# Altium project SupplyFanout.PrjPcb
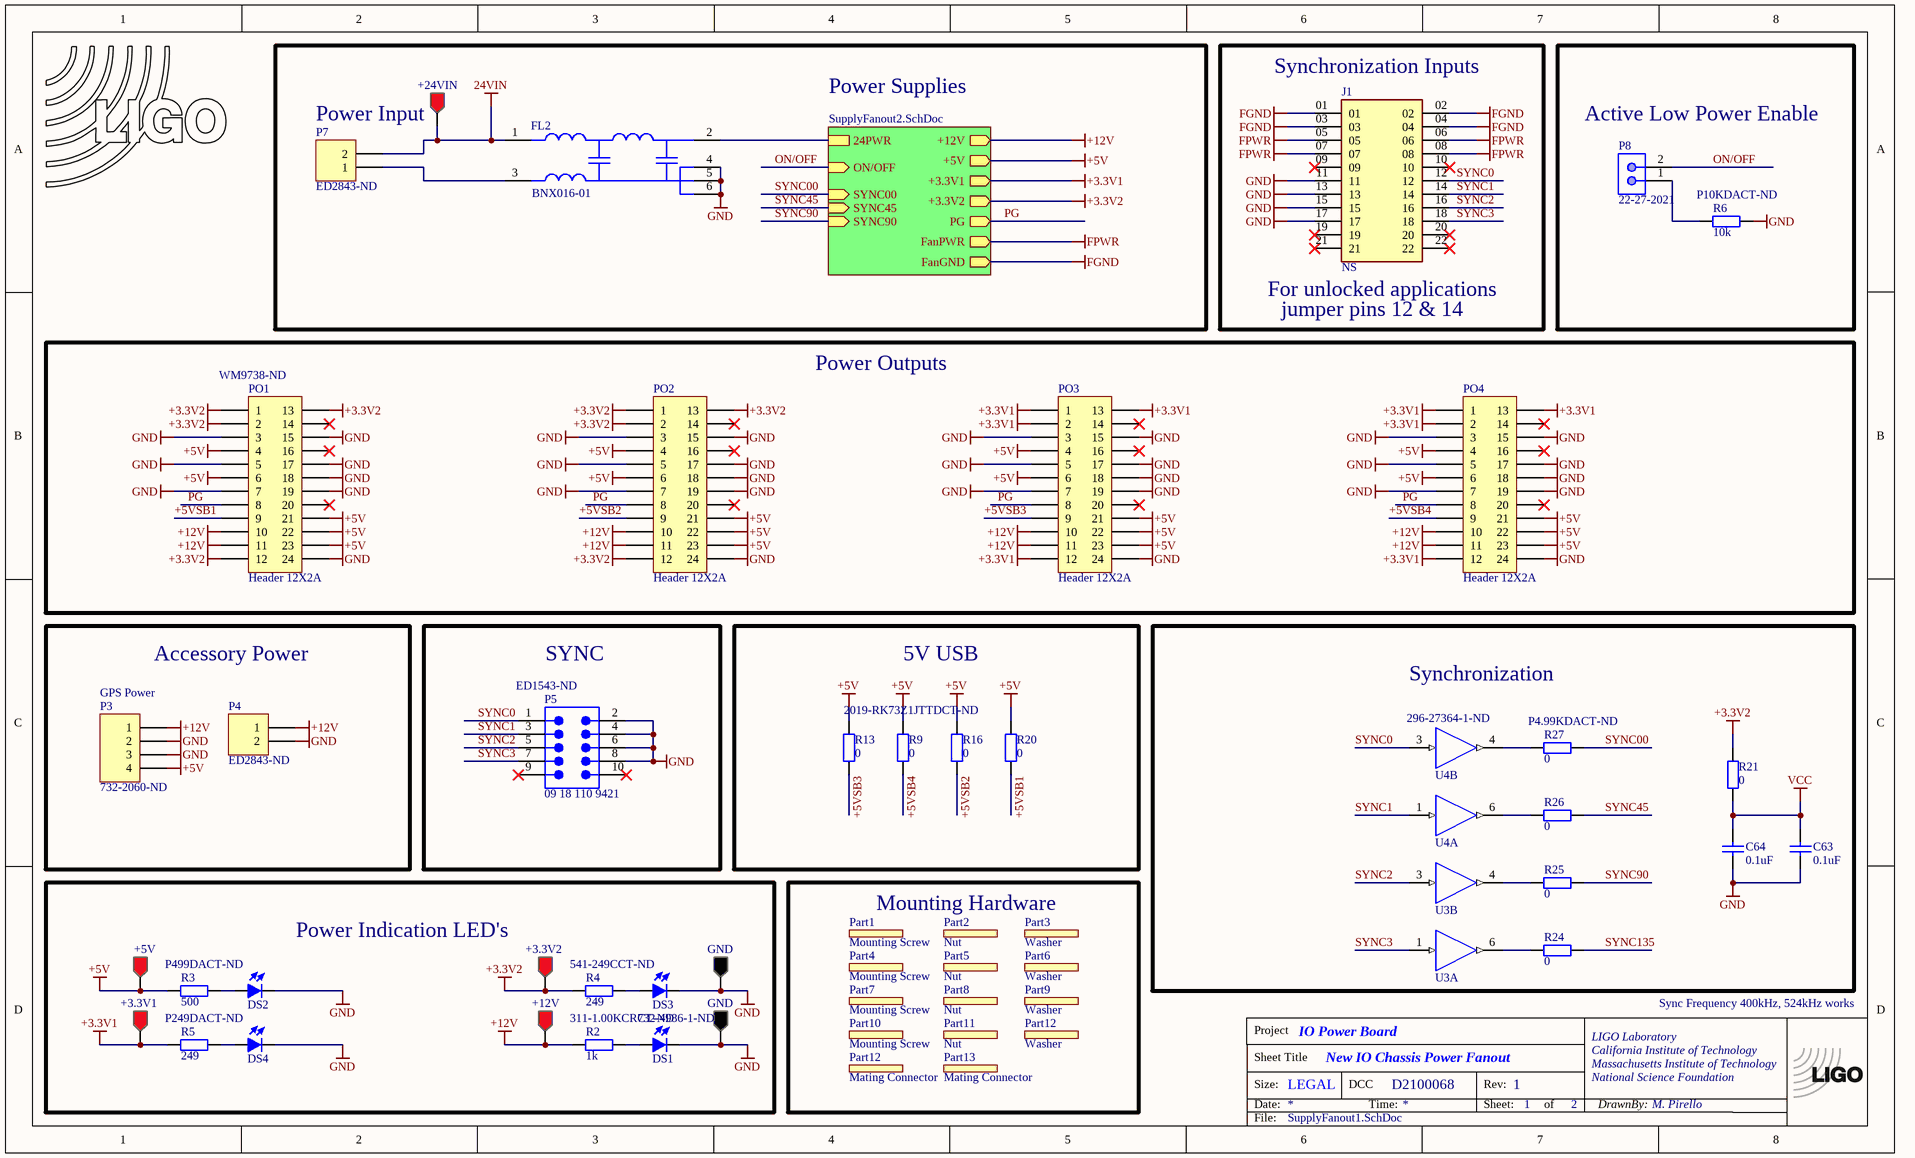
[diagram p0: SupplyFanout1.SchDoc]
DCC: D2100068; Eng: M. Pirello; PROJECT: IO Power Board; REV: 1; SHEETSIZE: LEGAL
2 sheets, 168 parts. Net scope: hierarchical (ports join the sheet entries above them; power ports are global).
Board file: SupplyFanout_30inch.PcbDoc
Sheets:
  SupplyFanout1.SchDoc
    Power Supplies = SupplyFanout2.SchDoc

## Sheet SupplyFanout1.SchDoc: New IO Chassis Power Fanout
size Legal; Organization: LIGO Project; Address1: California Institute of Technology; Address2: Massachusetts Institute of technology; DocumentNumber: D1800033; Revision: v1; SheetNumber: 1; SheetTotal: 2; Author: .Ben Abbott; DrawnBy: .Ben Abbott; Engineer: M. Pirello

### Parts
(Parts that share a designator on the sheet are numbered #1, #2 ... from top to bottom, then left to right.)
*?#1  TitleBlock  (value not drawn)  (graphical)
+3.3V1  Testpoint  [TP1-RED]  (value not drawn)
+3.3V2  Testpoint  [TP1-RED]  (value not drawn)
+5V  Testpoint  [TP1-RED]  (value not drawn)
+12V  Testpoint  [TP1-RED]  (value not drawn)
+24VIN  Testpoint  [TP1-RED]  (value not drawn)
C63  0.1uF  [CC1608-0603]
C64  0.1uF  [CC1608-0603]
DS1  Supplier Part Number 1: 732-4986-1-ND  [LED-0805]  (hidden comment: LED)
DS2  LED  [LED-0805]  (value not drawn)
DS3  LED  [LED-0805]  (value not drawn)
DS4  LED  [LED-0805]  (value not drawn)
FL2  BNX016-01  [MURA-BNX016-01_V]
GND#1  Testpoint  [TP1-BLK]  (value not drawn)
GND#2  Testpoint  [TP1-BLK]  (value not drawn)
J1  NS  [SAMTEC_SSW-111-02-G-D-RA]
LOGO2  LIGO logo  [LIGO-LOGO-SM]  (value not drawn)  (no BOM)
P3  Supplier Part Number 1: 732-2060-ND  [SL_5_08HC_180B_04]  (hidden comment: TBlock_5.08_4)
P4  Supplier Part Number 1: ED2843-ND  [SL_5_08HC_180B_02]  (hidden comment: TBlock_5.08_2)
P5  09 18 110 9421  Supplier Part Number 1: ED1543-ND  [9181109421]
P7  Supplier Part Number 1: ED2843-ND  [SL_5_08HC_180B_02]  (hidden comment: TBlock_5.08_2)
P8  22-27-2021  [MOLX-22-27-2021_V]
Part1  Mounting Screw  (mechanical)
Part2  Nut  (mechanical)
Part3  Washer  (mechanical)
Part4  Mounting Screw  (mechanical)
Part5  Nut  (mechanical)
Part6  Washer  (mechanical)
Part7  Mounting Screw  (mechanical)
Part8  Nut  (mechanical)
Part9  Washer  (mechanical)
Part10  Mounting Screw  (mechanical)
Part11  Nut  (mechanical)
Part12#1  Washer  (mechanical)
Part12#2  Mating Connector  (mechanical)
Part13  Mating Connector  (mechanical)
PO1  Header 12X2A  Supplier Part Number 1: WM9738-ND  [ATX24Pin_M]
PO2  Header 12X2A  [ATX24Pin_M]
PO3  Header 12X2A  [ATX24Pin_M]
PO4  Header 12X2A  [ATX24Pin_M]
R2  Supplier Part Number 1: 311-1.00KCRCT-ND  [CR2012-0805]  (hidden comment: 1k)
R3  Supplier Part Number 1: P499DACT-ND  [CR2012-0805]  (hidden comment: 500)
R4  Supplier Part Number 1: 541-249CCT-ND  [CR2012-0805]  (hidden comment: 249)
R5  Supplier Part Number 1: P249DACT-ND  [CR2012-0805]  (hidden comment: 249)
R6  Supplier Part Number 1: P10KDACT-ND  [CR2012-0805]  (hidden comment: 10k)
R9  0  [CR1608-0603]
R13  Supplier Part Number 1: 2019-RK73Z1JTTDCT-ND  [CR1608-0603]  (hidden comment: 0)
R16  0  [CR1608-0603]
R20  0  [CR1608-0603]
R21  0  [CR3216-1206]
R24  0  [CR3216-1206]
R25  0  [CR3216-1206]
R26  0  [CR3216-1206]
R27  Supplier Part Number 1: P4.99KDACT-ND  [CR3216-1206]  (hidden comment: 0)
U3  SN74LVC2G34  [SO-G6/E2.4]  (value not drawn)  (parts A,B of 2)
U4  SN74LVC2G34  [SO-G6/E2.4]  (value not drawn)  (parts A,B of 2)

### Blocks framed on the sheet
Power Input: +24VIN FL2 P7
Active Low Power Enable: P8 R6
Power Outputs: PO1-PO4
Accessory Power: P3 P4
SYNC: P5
5V USB: R9 R13 R16 R20
Synchronization: C63 C64 R21 R24-R27 U3 U4
Power Indication LED's: +3.3V1 +3.3V2 +5V +12V DS1-DS4 GND#1 GND#2 R2-R5
Mounting Hardware: Part1-Part11 Part12#1 Part12#2 Part13

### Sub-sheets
Power Supplies = SupplyFanout2.SchDoc: 24PWR, SYNC00 (in), SYNC45 (in), SYNC90 (in), ON/OFF (in), PG (out), +3.3V1 (out), +3.3V2 (out), +5V (out), +12V (out), FanPWR (out), FanGND (out)

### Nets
24VIN: +24VIN.1 FL2.1(B) P7.2
+3.3V1: +3.3V1.1 PO3.1 PO3.2 PO3.12 PO3.13 PO4.1 PO4.2 PO4.12 PO4.13 R5.1 ; sheet Power Supplies/+3.3V1
+3.3V2: +3.3V2.1 PO1.1 PO1.2 PO1.12 PO1.13 PO2.1 PO2.2 PO2.12 PO2.13 R4.1 R21.1 ; sheet Power Supplies/+3.3V2
+5V: +5V.1 P3.4 PO1.4 PO1.6 PO1.21 PO1.22 PO1.23 PO2.4 PO2.6 PO2.21 PO2.22 PO2.23 PO3.4 PO3.6 PO3.21 PO3.22 PO3.23 PO4.4 PO4.6 PO4.21 PO4.22 PO4.23 R3.1 R9.1 R13.1 R16.1 R20.1 ; sheet Power Supplies/+5V
+12V: +12V.1 P3.1 P4.1 PO1.10 PO1.11 PO2.10 PO2.11 PO3.10 PO3.11 PO4.10 PO4.11 R2.1 ; sheet Power Supplies/+12V
FGND: J1.01 J1.02 J1.03 J1.04 ; sheet Power Supplies/FanGND
FPWR: J1.05 J1.06 J1.07 J1.08 ; sheet Power Supplies/FanPWR
GND: C63.1 C64.1 DS1.1(K) DS2.1(K) DS3.1(K) DS4.1(K) FL2.4(CG) FL2.5(CG) FL2.6(CG) GND#1.1 GND#2.1 J1.11 J1.13 J1.15 J1.17 P3.2 P3.3 P4.2 P5.2 P5.4 P5.6 P5.8 PO1.3 PO1.5 PO1.7 PO1.15 PO1.17 PO1.18 PO1.19 PO1.24 PO2.3 PO2.5 PO2.7 PO2.15 PO2.17 PO2.18 PO2.19 PO2.24 PO3.3 PO3.5 PO3.7 PO3.15 PO3.17 PO3.18 PO3.19 PO3.24 PO4.3 PO4.5 PO4.7 PO4.15 PO4.17 PO4.18 PO4.19 PO4.24 R6.1 U3.2(GND) U4.2(GND)
VCC: C63.2 C64.2 R21.2 U3.5(VCC) U4.5(VCC)
+5VSB1: PO1.9 R20.2
+5VSB2: PO2.9 R16.2
+5VSB3: PO3.9 R13.2
+5VSB4: PO4.9 R9.2
ON/OFF: P8.2 ; sheet Power Supplies/ON/OFF
PG: PO1.8 PO2.8 PO3.8 PO4.8 ; sheet Power Supplies/PG
SYNC00: R27.1 ; sheet Power Supplies/SYNC00
SYNC0: J1.12 P5.1 U4.3(2A)
SYNC1: J1.14 P5.3 U4.1(1A)
SYNC2: J1.16 P5.5 U3.3(2A)
SYNC3: J1.18 P5.7 U3.1(1A)
SYNC45: R26.1 ; sheet Power Supplies/SYNC45
SYNC90: R25.1 ; sheet Power Supplies/SYNC90
SYNC135: R24.1
Net+24V_1: FL2.2(CB) ; sheet Power Supplies/24PWR
NetDS1_2: DS1.2(A) R2.2
NetDS2_2: DS2.2(A) R3.2
NetDS3_2: DS3.2(A) R4.2
NetDS4_2: DS4.2(A) R5.2
NetFL2_3: FL2.3(PSG) P7.1
NetP8_1: P8.1 R6.2
NetR24_2: R24.2 U3.6(1Y)
NetR25_2: R25.2 U3.4(2Y)
NetR26_2: R26.2 U4.6(1Y)
NetR27_2: R27.2 U4.4(2Y)

Not connected (* = marked no-connect by the designer): J1 09* 10* 19* 20* 21* 22*; P5 9* 10*; PO1 14* 16* 20*; PO2 14* 16* 20*; PO3 14* 16* 20*; PO4 14* 16* 20*

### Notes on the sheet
- (near J1) Synchronization Inputs
- (near J1) For unlocked applications
- (near J1) jumper pins 12 & 14
- (near P3) GPS Power
- Sync Frequency 400kHz, 524kHz works

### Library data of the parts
+3.3V1 +3.3V2 +5V +12V +24VIN = TP_POSITIVE: Testpoint, red; Part Number: 36-5005-ND
C63 C64 = ChipCap: Capacitor, surface mount; Tolerance: 10%
DS1-DS4 = LED: Panel mount LED
FL2 = CMP-2000-05960-1: Block Type EMIFIL(R) Reference Specification, 15 A, 25 V, -40 to 125 degC, 6-Pin THD, RoHS, Bulk; Part Number: 490-5055-ND
GND#1 GND#2 = TP_GND: Testpoint, black; Part Number: 36-5006-ND
J1 = SSW-111-02-G-D-RA: MF: Samtec Inc.
LOGO2 = LIGO_logo
P3 = TBlock_5.08_4: Terminal block, 5.08mm, 4-Pin; Part Number: 281-1299-ND
P4 P7 = TBlock_5.08_2: Terminal block, 5.08mm, 2-Pin; Part Number: 281-1297-ND
P5 = 09 18 110 9421: Flat Cable Connector (IDC), PCB Transition Connector, 2 Rows, Kinked Solder Pin, 10 Contacts; PCB_Layout: Complies with manufacturer's recommendation.; DrillSize: Corresponds to nominal value.
P8 = CMP-2000-05537-1: Male Header, Pitch 2.54 mm, 1 x 2 Position, Height 11.7 mm, Tail Length 3.56 mm, 0 to 75 degC, RoHS, Bulk; Manufacturer: Molex; PartNumber: 0022272021; Current rating: 4A; Package Version: Rev. BC, 02/2012; Voltage rating: 250V; No. of Positions: 2; Pitch: 2.54mm; No. of Rows: 1
Part1 Part4 Part7 Part10 = Mechanical Part: Mounting Screw for Inductors
Part2 Part5 Part8 Part11 = Mechanical Part: Nut for Inductor Mounting Screw
Part3 Part6 Part9 Part12#1 Part12#2 Part13 = Mechanical Part: To go under nut for Inductor Mounting Screw
PO1 = ATX24PIN_MALE: Header, 12-Pin, Dual row, ATX power, board
PO2-PO4 = ATX24PIN_MALE: Header, 12-Pin, Dual row, ATX power, board; Part Number: WM9738-ND
R2-R6 R9 R13 R16 R20 R21 R24-R27 = ChipRes1: Resistor, surface mount; Tolerance: 1%
U3 U4 = SN74LVC2G34: Dual buffer

## Sheet SupplyFanout2.SchDoc: New IO Chassis Power Fanout
size Legal; Organization: LIGO Project; Address1: California Institute of Technology; Address2: Massachusetts Institute of technology; DocumentNumber: D1800033; Revision: v1; SheetNumber: 2; SheetTotal: 2; Author: .Ben Abbott; DrawnBy: .Ben Abbott; Engineer: M. Pirello
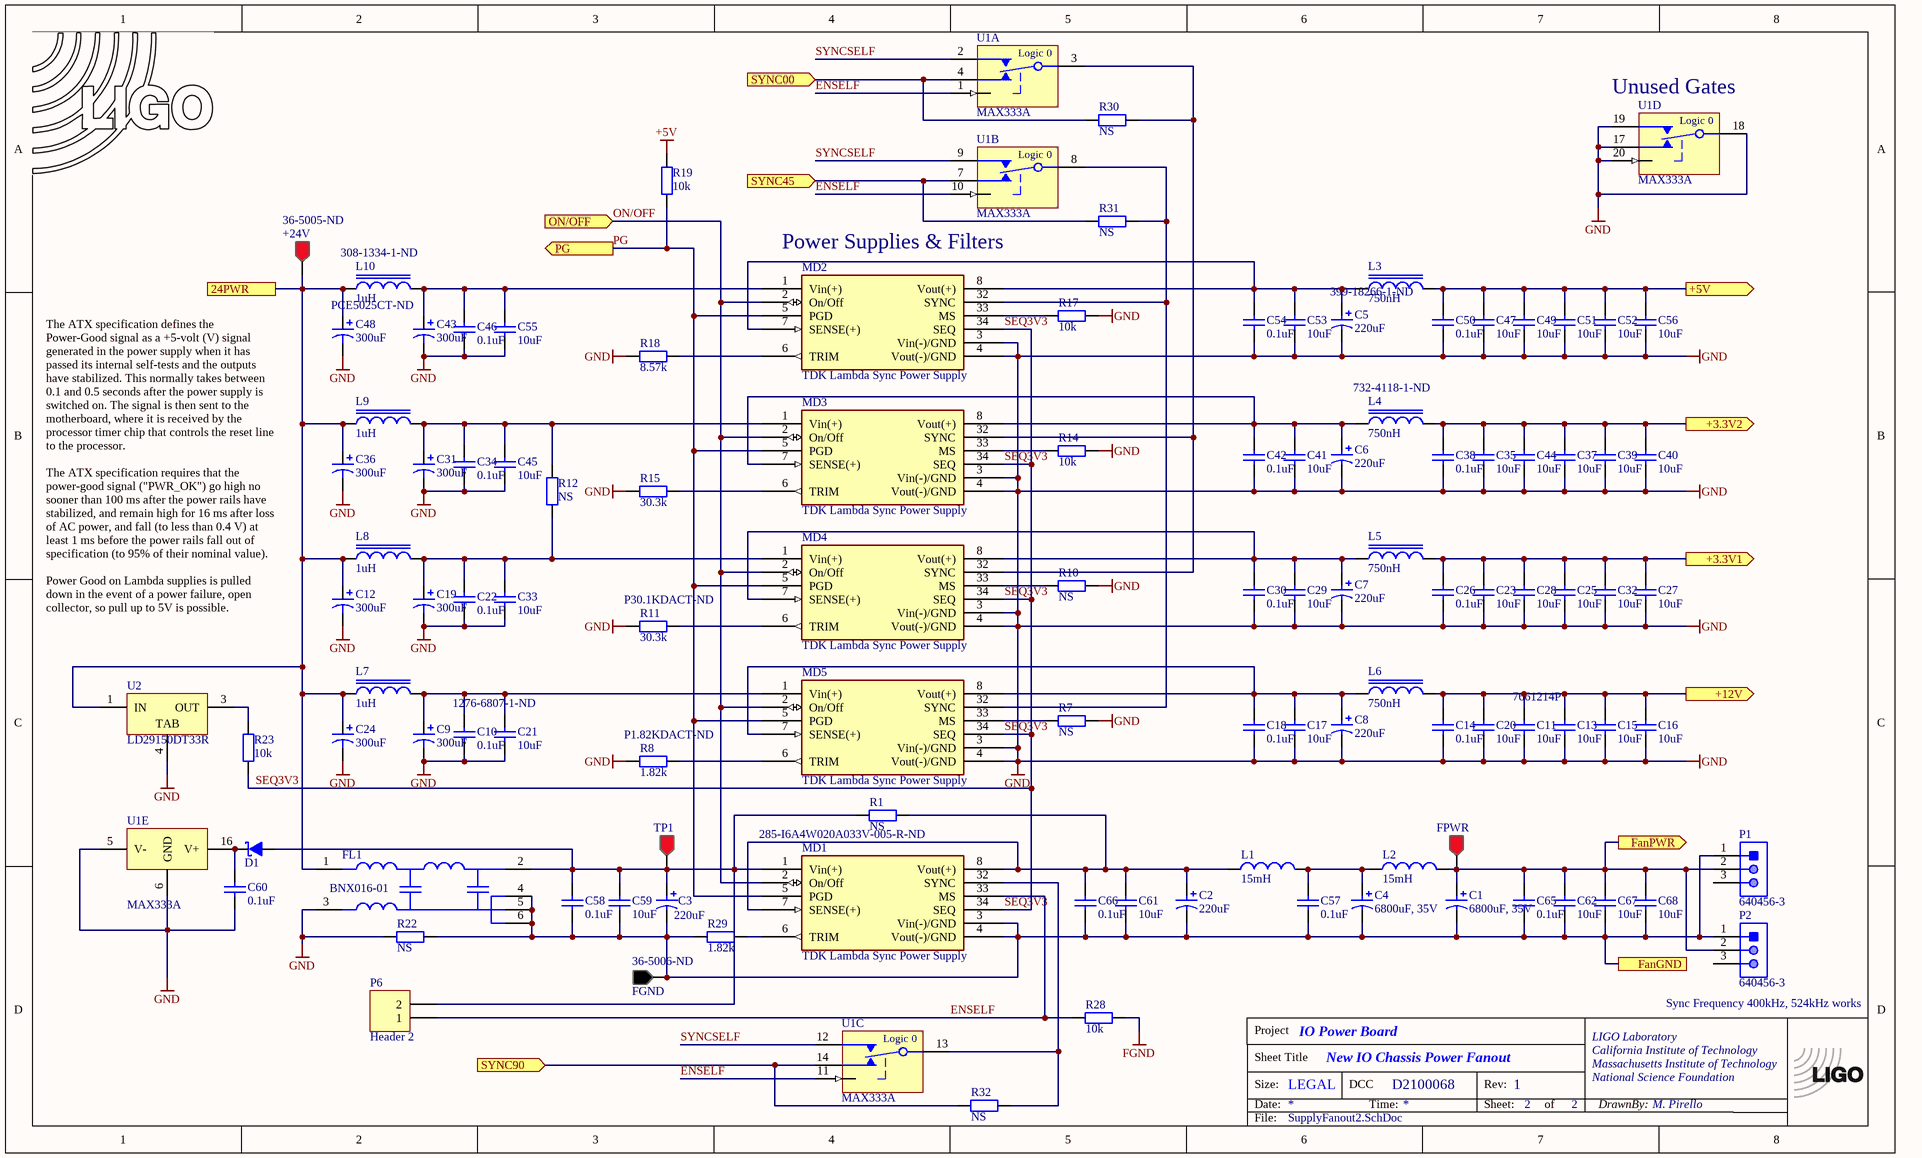
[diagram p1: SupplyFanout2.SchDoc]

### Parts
(Parts that share a designator on the sheet are numbered #1, #2 ... from top to bottom, then left to right.)
*?#2  TitleBlock  (value not drawn)  (graphical)
+24V  Supplier Part Number 1: 36-5005-ND  [TP1-RED]  (hidden comment: Testpoint)
C1  6800uF, 35V  [RB18/7.5]
C2  220uF  [RB10/5.0]
C3  220uF  [RB10/5.0]
C4  6800uF, 35V  [RB18/7.5]
C5  Supplier Part Number 1: 399-18266-1-ND  [RB10/5.0]  (hidden comment: 220uF)
C6  220uF  [RB10/5.0]
C7  220uF  [RB10/5.0]
C8  220uF  [RB10/5.0]
C9  300uF  [AC083-033/E]
C10  Supplier Part Number 1: 1276-6807-1-ND  [CC1608-0603]  (hidden comment: 0.1uF)
C11  Supplier Part Number 1: 7661214P  [CC3225-1210]  (hidden comment: 10uF)
C12  300uF  [AC083-033/E]
C13  10uF  [CC3225-1210]
C14  0.1uF  [CC1608-0603]
C15  10uF  [CC3225-1210]
C16  10uF  [CC3225-1210]
C17  10uF  [CC3225-1210]
C18  0.1uF  [CC1608-0603]
C19  300uF  [AC083-033/E]
C20  10uF  [CC3225-1210]
C21  10uF  [CC3225-1210]
C22  0.1uF  [CC1608-0603]
C23  10uF  [CC3225-1210]
C24  300uF  [AC083-033/E]
C25  10uF  [CC3225-1210]
C26  0.1uF  [CC1608-0603]
C27  10uF  [CC3225-1210]
C28  10uF  [CC3225-1210]
C29  10uF  [CC3225-1210]
C30  0.1uF  [CC1608-0603]
C31  300uF  [AC083-033/E]
C32  10uF  [CC3225-1210]
C33  10uF  [CC3225-1210]
C34  0.1uF  [CC1608-0603]
C35  10uF  [CC3225-1210]
C36  300uF  [AC083-033/E]
C37  10uF  [CC3225-1210]
C38  0.1uF  [CC1608-0603]
C39  10uF  [CC3225-1210]
C40  10uF  [CC3225-1210]
C41  10uF  [CC3225-1210]
C42  0.1uF  [CC1608-0603]
C43  300uF  [AC083-033/E]
C44  10uF  [CC3225-1210]
C45  10uF  [CC3225-1210]
C46  0.1uF  [CC1608-0603]
C47  10uF  [CC3225-1210]
C48  Supplier Part Number 1: PCE5025CT-ND  [AC083-033/E]  (hidden comment: 300uF)
C49  10uF  [CC3225-1210]
C50  0.1uF  [CC1608-0603]
C51  10uF  [CC3225-1210]
C52  10uF  [CC3225-1210]
C53  10uF  [CC3225-1210]
C54  0.1uF  [CC1608-0603]
C55  10uF  [CC3225-1210]
C56  10uF  [CC3225-1210]
C57  0.1uF  [CC1608-0603]
C58  0.1uF  [CC1608-0603]
C59  10uF  [CC3225-1210]
C60  0.1uF  [CC1608-0603]
C61  10uF  [CC3225-1210]
C62  10uF  [CC3225-1210]
C65  0.1uF  [CC1608-0603]
C66  0.1uF  [CC1608-0603]
C67  10uF  [CC3225-1210]
C68  10uF  [CC3225-1210]
D1  shottky diode  [DO-SMA]  (value not drawn)
FGND  Supplier Part Number 1: 36-5006-ND  [TP1-BLK]  (hidden comment: Testpoint)
FL1  BNX016-01  [MURA-BNX016-01_V]
FPWR  Testpoint  [TP1-RED]  (value not drawn)
L1  value 15mH  [Rnd Inductor 45D]  (hidden comment: Inductor)
L2  value 15mH  [Rnd Inductor 45D]  (hidden comment: Inductor)
L3  750nH  [MSS1278]
L4  Supplier Part Number 1: 732-4118-1-ND  [MSS1278]  (hidden comment: 750nH)
L5  750nH  [MSS1278]
L6  750nH  [MSS1278]
L7  1uH  [MSS1278]
L8  1uH  [MSS1278]
L9  1uH  [MSS1278]
L10  Supplier Part Number 1: 308-1334-1-ND  [MSS1278]  (hidden comment: 1uH)
LOGO1  LIGO logo  [LIGO_LOGO]  (value not drawn)  (no BOM)
MD1  TDK Lambda Sync Power Supply  Supplier Part Number 1: 285-I6A4W020A033V-005-R-ND  [TDK-Lambda]
MD2  TDK Lambda Sync Power Supply  [TDK-Lambda]
MD3  TDK Lambda Sync Power Supply  [TDK-Lambda]
MD4  TDK Lambda Sync Power Supply  [TDK-Lambda]
MD5  TDK Lambda Sync Power Supply  [TDK-Lambda]
P1  640456-3  [TECO-640456-3]
P2  640456-3  [TECO-640456-3]
P6  Header 2  [HDR1X2]
R1  NS  [CR3225-1210]
R7  NS  [CR1608-0603]
R8  Supplier Part Number 1: P1.82KDACT-ND  [CR2012-0805]  (hidden comment: 1.82k)
R10  NS  [CR1608-0603]
R11  Supplier Part Number 1: P30.1KDACT-ND  [CR2012-0805]  (hidden comment: 30.3k)
R12  NS  [CR3225-1210]
R14  10k  [CR1608-0603]
R15  30.3k  [CR2012-0805]
R17  10k  [CR1608-0603]
R18  8.57k  [CR2012-0805]
R19  10k  [CR1608-0603]
R22  NS  [CR3225-1210]
R23  10k  [CR1608-0603]
R28  10k  [CR1608-0603]
R29  1.82k  [CR2012-0805]
R30  NS  [CR0603-0201]
R31  NS  [CR0603-0201]
R32  NS  [CR0603-0201]
TP1  Testpoint  [TP1-RED]  (value not drawn)
U1  MAX333A  [SO-G20]  (parts A,B,C,D,E of 5)
U2  LD29150DT33R  [TO-252_L]

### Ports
24PWR, +3.3V1 (out), +3.3V2 (out), +5V (out), +12V (out), FanGND, FanPWR (out), ON/OFF (in), PG (out), SYNC00 (in), SYNC45 (in), SYNC90 (in)

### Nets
+3.3V1: C23.2 C25.2 C26.2 C27.2 C28.2 C32.2 L5.2 ; port +3.3V1
+3.3V2: C35.2 C37.2 C38.2 C39.2 C40.2 C44.2 L4.2 ; port +3.3V2
+5V: C47.2 C49.2 C50.2 C51.2 C52.2 C56.2 L3.2 R19.1 ; port +5V
+12V: C11.2 C13.2 C14.2 C15.2 C16.2 C20.2 L6.2 ; port +12V
FGND: C1.2 C2.2 C3.2 C4.2 C57.1 C58.1 C59.1 C61.1 C62.1 C65.1 C66.1 C67.1 C68.1 FGND.1 FL1.4(CG) FL1.5(CG) FL1.6(CG) MD1.3(Vin(-)/GND) MD1.4(Vout(-)/GND) P1.1 P2.1 R22.1 R28.2 R29.2 ; port FanGND
FPWR: C1.1 C62.2 C65.2 C67.2 C68.2 FPWR.1 L2.1 P1.2 P2.2 ; port FanPWR
GND: C5.2 C6.2 C7.2 C8.2 C9.2 C10.1 C11.1 C12.2 C13.1 C14.1 C15.1 C16.1 C17.1 C18.1 C19.2 C20.1 C21.1 C22.1 C23.1 C24.2 C25.1 C26.1 C27.1 C28.1 C29.1 C30.1 C31.2 C32.1 C33.1 C34.1 C35.1 C36.2 C37.1 C38.1 C39.1 C40.1 C41.1 C42.1 C43.2 C44.1 C45.1 C46.1 C47.1 C48.2 C49.1 C50.1 C51.1 C52.1 C53.1 C54.1 C55.1 C56.1 C60.1 FL1.3(PSG) MD2.3(Vin(-)/GND) MD2.4(Vout(-)/GND) MD3.3(Vin(-)/GND) MD3.4(Vout(-)/GND) MD4.3(Vin(-)/GND) MD4.4(Vout(-)/GND) MD5.3(Vin(-)/GND) MD5.4(Vout(-)/GND) R7.2 R8.2 R10.2 R11.2 R14.2 R15.2 R17.2 R18.2 R22.2 U1.5(V-) U1.6(GND) U1.17(NO4) U1.18(COM4) U1.19(NC4) U1.20(IN4) U2.4(TAB)
ENSELF: MD1.33(MS) P6.1 R28.1 U1.1(IN1) U1.10(IN2) U1.11(IN3)
ON/OFF: MD1.2(On/Off) MD2.2(On/Off) MD3.2(On/Off) MD4.2(On/Off) MD5.2(On/Off) ; port ON/OFF
PG: MD1.5(PGD) MD2.5(PGD) MD3.5(PGD) MD4.5(PGD) MD5.5(PGD) R19.2 ; port PG
SEQ3V3: MD1.34(SEQ) MD2.34(SEQ) MD3.34(SEQ) MD4.34(SEQ) MD5.34(SEQ) R23.1
SYNC00: R30.1 U1.4(NO1) ; port SYNC00
SYNC45: R31.1 U1.7(NO2) ; port SYNC45
SYNC90: R32.1 U1.14(NO3) ; port SYNC90
SYNCSELF: U1.2(NC1) U1.9(NC2) U1.12(NC3)
Net+24V_1: +24V.1 C12.1 C24.1 C36.1 C48.1 FL1.1(B) L7.1 L8.1 L9.1 L10.1 U2.1(IN) ; port 24PWR
NetC2_1: C2.1 C61.2 C66.2 L1.2 MD1.7(SENSE(+)) MD1.8(Vout(+)) R1.1
NetC3_1: C3.1 C58.2 C59.2 D1.1(A) FL1.2(CB) MD1.1(Vin(+)) P6.2 R1.2 TP1.1
NetC4_1: C4.1 C57.2 L1.1 L2.2
NetC5_1: C5.1 C53.2 C54.2 L3.1 MD2.7(SENSE(+)) MD2.8(Vout(+))
NetC6_1: C6.1 C41.2 C42.2 L4.1 MD3.7(SENSE(+)) MD3.8(Vout(+))
NetC7_1: C7.1 C29.2 C30.2 L5.1 MD4.7(SENSE(+)) MD4.8(Vout(+))
NetC8_1: C8.1 C17.2 C18.2 L6.1 MD5.7(SENSE(+)) MD5.8(Vout(+))
NetC9_1: C9.1 C10.2 C21.2 L7.2 MD5.1(Vin(+))
NetC19_1: C19.1 C22.2 C33.2 L8.2 MD4.1(Vin(+)) R12.2
NetC31_1: C31.1 C34.2 C45.2 L9.2 MD3.1(Vin(+)) R12.1
NetC43_1: C43.1 C46.2 C55.2 L10.2 MD2.1(Vin(+))
NetC60_2: C60.2 D1.2(K) U1.16(V+)
NetMD1_6: MD1.6(TRIM) R29.1
NetMD1_32: MD1.32(SYNC) R32.2 U1.13(COM3)
NetMD2_6: MD2.6(TRIM) R18.1
NetMD2_32: MD2.32(SYNC) MD5.32(SYNC) R31.2 U1.8(COM2)
NetMD2_33: MD2.33(MS) R17.1
NetMD3_6: MD3.6(TRIM) R15.1
NetMD3_32: MD3.32(SYNC) MD4.32(SYNC) R30.2 U1.3(COM1)
NetMD3_33: MD3.33(MS) R14.1
NetMD4_6: MD4.6(TRIM) R11.1
NetMD4_33: MD4.33(MS) R10.1
NetMD5_6: MD5.6(TRIM) R8.1
NetMD5_33: MD5.33(MS) R7.1
NetR23_2: R23.2 U2.3(OUT)

Not connected (* = marked no-connect by the designer): P1 3; P2 3; U1 15(N.C.)

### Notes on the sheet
- (near U1) Unused Gates
- Power Supplies & Filters
- The ATX specification defines the Power-Good signal as a +5-volt (V) signal generated in the power supply when it has passed its internal self-tests and the outputs have stabilized. This normally takes between 0.1 and 0.5 seconds after the power supply is switched on. The signal is then sent to the motherboard, where it is received by the processor timer chip that controls the reset line to the processor.
  The ATX specification requires that the power-good signal ("PWR_OK") go high no sooner than 100 ms after the power rails have stabilized, and remain high for 16 ms after loss of AC power, and fall (to less than 0.4 V) at least 1 ms before the power rails fall out of specification (to 95% of their nominal value).
  Power Good on Lambda supplies is pulled down in the event of a power failure, open collector, so pull up to 5V is possible.
- (near P2) Sync Frequency 400kHz, 524kHz works

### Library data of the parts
+24V = TP_POSITIVE: Testpoint, red
C1 C4 = CapRadial: Electrolyte capacitor, leaded, radial / 1189-3996-ND; Manufacturer: Nichicon; Tolerance: 20%
C2 C3 C5-C8 = CapRadial: Electrolyte capacitor, leaded, radial; Manufacturer: Nichicon; Tolerance: 20%
C9 C12 C19 C24 C31 C36 C43 C48 = ChipElectrolyte: Electrolyte capacitor, surface mount; Tolerance: 20%; Voltage Rating: 50V
C10 C11 C13-C18 C20-C23 C25-C30 C32-C35 C37-C42 C44-C47 C49-C62 C65-C68 = ChipCap: Capacitor, surface mount; Tolerance: 10%
D1 = DIODE_SHOTTKY: Single shottky diode
FGND = TP_GND: Testpoint, black
FL1 = CMP-2000-05960-1: as FL2 on sheet SupplyFanout1
FPWR TP1 = TP_POSITIVE: Testpoint, red; Part Number: 36-5005-ND
L3-L10 = MSS1278: Power inductor, MSS1278 series
LOGO1 = LIGO_logo
MD1-MD5 = TDK-Lambda: i6A4W020A033V-005-R
P1 P2 = CMP-2000-05418-1: Male Header, Pitch 2.54 mm, 1 x 3 Position, Height 10.03 mm, Tail Length 3.56 mm, -55 to 105 degC; Manufacturer: TE Connectivity; Agency Approvals: CSA,UL; Angle: Straight; Number of Positions: 3; Standards: RoHSCompliant,ELVCompliant,UL94V-0; Current, Rating: 5 / A; Connector Type: MTA-100; Mount Angle: Vertical; Material, Housing: Polyester; Temperature, Operating: -55to+105 / degC; Voltage, Rating: 250 / V; Color, Housing: White; Contact Centerline Spacing: 0.100 / in.; Special Features: Pinstrip; Material, Contact: CopperAlloy; Contact Termination Area Plating: Tin; Primary Type: InterconnectSystem; Pin Spacing: 0.1 / "; Brand/Series: MTA-100Series; Mounting Hole Size: 0.04 / "
P6 = Header 2: Header, 2-Pin
R1 R7 R8 R10-R12 R14 R15 R17-R19 R22 R23 R28-R32 = ChipRes1: Resistor, surface mount; Tolerance: 1%
U1 = MAX333Acompact: Quad SPDT analog switch; Part Number: MAX333AEWP+-ND
U2 = CMP-0244-00130-1: 1.5A, Very-Low Drop Voltage Regulator, 3.3V, 3-Pin DPAK

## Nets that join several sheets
+3.3V1: SupplyFanout1 (10 pins), SupplyFanout2 (7 pins)
+3.3V2: SupplyFanout1 (11 pins), SupplyFanout2 (7 pins)
+5V: SupplyFanout1 (27 pins), SupplyFanout2 (8 pins)
+12V: SupplyFanout1 (12 pins), SupplyFanout2 (7 pins)
FGND: SupplyFanout1 (J1.01 J1.02 J1.03 J1.04), SupplyFanout2 (24 pins)
FPWR: SupplyFanout1 (J1.05 J1.06 J1.07 J1.08), SupplyFanout2 (9 pins)
GND: SupplyFanout1 (57 pins), SupplyFanout2 (78 pins)
Net+24V_1: SupplyFanout1 (FL2.2), SupplyFanout2 (11 pins)
ON/OFF: SupplyFanout1 (P8.2), SupplyFanout2 (5 pins)
PG: SupplyFanout1 (PO1.8 PO2.8 PO3.8 PO4.8), SupplyFanout2 (6 pins)
SYNC00: SupplyFanout1 (R27.1), SupplyFanout2 (R30.1 U1.4)
SYNC45: SupplyFanout1 (R26.1), SupplyFanout2 (R31.1 U1.7)
SYNC90: SupplyFanout1 (R25.1), SupplyFanout2 (R32.1 U1.14)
